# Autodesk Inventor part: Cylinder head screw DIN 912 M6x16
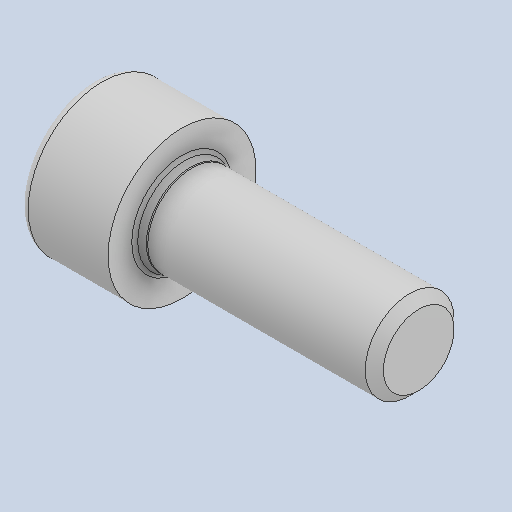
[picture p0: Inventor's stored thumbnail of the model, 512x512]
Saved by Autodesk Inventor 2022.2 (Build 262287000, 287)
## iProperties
Created: 2024-10
Part Number: Cylinder head screw DIN 912 M6x16
Material: Generico
Document SubType Name: Modeling
Designer: 18907419
Density: 1 g/cm^3
Appearance: Default
Author: 18907419
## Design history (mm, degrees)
feature "Solid1"
node "Solido1"
